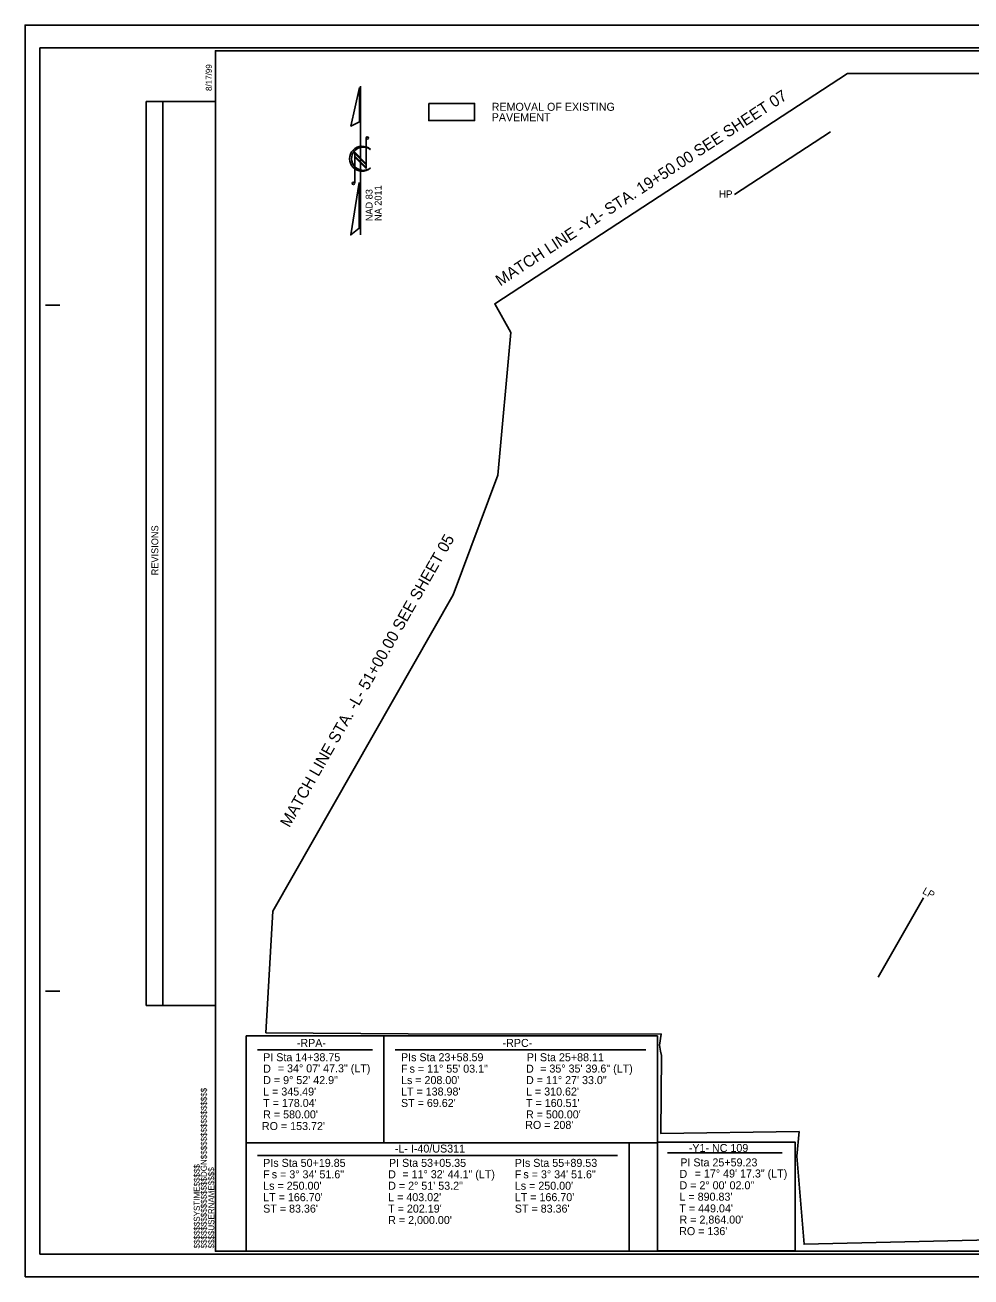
# Model space of a CAD drawing. Extents: x 1639431 to 1642602, y 841916 to 843940.
# Drawn here: x 1640204 to 1641031, y 841916 to 843011 of the extents above; entities that cross this region are included whole.
import ezdxf

# ---------------------------------------------------------------- set-up
doc = ezdxf.new("R2010")
doc.units = 0
for name, color, linetype in [('Default', 7, 'Continuous'), ('Matchline', 7, 'Continuous'), ('Matchline Text', 7, 'Continuous'), ('Old_Level_1', 7, 'Continuous'), ('Prop Horizontal Alignment Curve and Spiral Data', 7, 'Continuous'), ('Prop Rem of Exist Asph Pvmt', 7, 'Continuous'), ('Sheet Block Revision CELL', 7, 'Continuous'), ('Sheet Clip Boundary CELL', 7, 'Continuous'), ('Sheet Cutting Line CELL', 7, 'Continuous'), ('Sheet North Arrow CELL', 7, 'Continuous'), ('Sheet Plan CELL', 7, 'Continuous'), ('Sheet Plot Border Inside CELL', 7, 'Continuous'), ('Sheet Plot Border Outside CELL', 7, 'Continuous')]:
    doc.layers.add(name, color=color, linetype=linetype)

msp = doc.modelspace()

# ---------------------------------------------------------------- linework, layer by layer
at = {"layer": 'Matchline'}
msp.add_lwpolyline([(1640420.8, 842236.2), (1640420.8, 842236.2), (1640578.7, 842512.8), (1640617.7, 842617.6), (1640629.1, 842742.4), (1640615, 842767.5), (1640923.5, 842968.8)], dxfattribs=at)
at = {"layer": 'Old_Level_1'}
for p, q in [((1640908.4, 842917.8), (1640824.6, 842863.2)), ((1640950.2, 842178.6), (1640989.8, 842248))]:
    msp.add_line(p, q, dxfattribs=at)
at = {"layer": 'Prop Horizontal Alignment Curve and Spiral Data'}
for p, q in [((1640407.5, 842115), (1640508, 842115)), ((1640528, 842115), (1640747.2, 842115)), ((1640407.5, 842022.6), (1640722.4, 842022.6)), ((1640765.9, 842024.9), (1640866.4, 842024.9))]:
    msp.add_line(p, q, dxfattribs=at)
for points in [[(1640397.5, 842127.2), (1640518, 842127.2), (1640518, 842033.7), (1640397.5, 842033.7)], [(1640518, 842127.2), (1640757.2, 842127.2), (1640757.2, 842033.7), (1640518, 842033.7)], [(1640397.5, 842033.7), (1640732.4, 842033.7), (1640732.4, 841938.8), (1640397.5, 841938.8)], [(1640757.2, 842034.2), (1640877.7, 842034.2), (1640877.7, 841939.3), (1640757.2, 841939.3)]]:
    msp.add_lwpolyline(points, close=True, dxfattribs=at)
at = {"layer": 'Prop Rem of Exist Asph Pvmt'}
msp.add_lwpolyline([(1640557.3, 842942.7), (1640557.3, 842927.7), (1640597.3, 842927.7), (1640597.3, 842942.7)], close=True, dxfattribs=at)
at = {"layer": 'Sheet Block Revision CELL'}
msp.add_line((1640324.8, 842153.8), (1640324.8, 842944.5), dxfattribs=at)
msp.add_lwpolyline([(1640310.3, 842153.8), (1640310.3, 842944.4), (1640370.8, 842944.5), (1640370.8, 842153.8)], close=True, dxfattribs=at)
at = {"layer": 'Sheet Clip Boundary CELL'}
msp.add_line((1640923.5, 842968.8), (1641358.9, 842968.8), dxfattribs=at)
for points in [[(1640414.8, 842129.8), (1640420.8, 842236.2), (1640578.7, 842512.8), (1640617.7, 842617.6), (1640629.1, 842742.4), (1640615, 842767.5), (1640923.5, 842968.8)], [(1641627.1, 841958.8), (1641476.3, 841958.8), (1640885.4, 841944.9), (1640879, 842022.1), (1640881.1, 842043.4), (1640760.2, 842041.7), (1640760.7, 842110.1), (1640760, 842113.9), (1640759.1, 842119), (1640760.5, 842128.8), (1640539.4, 842129), (1640414.8, 842129.8)]]:
    msp.add_lwpolyline(points, dxfattribs=at)
at = {"layer": 'Sheet Cutting Line CELL'}
for p, q in [((1640204.3, 843011.3), (1640204.3, 841916.3)), ((1640204.3, 841916.3), (1641887.8, 841916.3))]:
    msp.add_line(p, q, dxfattribs=at)
at = {"layer": 'Sheet North Arrow CELL'}
for p, q in [((1640497.5, 842827.8), (1640497.5, 842957.8)), ((1640502.4, 842912.6), (1640502.4, 842885.9)), ((1640502.4, 842890), (1640492.5, 842900)), ((1640492.5, 842900), (1640492.5, 842872.9)), ((1640502.4, 842889.1), (1640492.5, 842899)), ((1640492.5, 842899), (1640492.5, 842896.6)), ((1640506.1, 842902.6), (1640506.3, 842902.5)), ((1640502.4, 842886.6), (1640492.5, 842896.6)), ((1640492.5, 842896.6), (1640502.4, 842886.6)), ((1640502.4, 842885.9), (1640492.5, 842895.8)), ((1640502.4, 842886.6), (1640502.4, 842889.1))]:
    msp.add_line(p, q, dxfattribs=at)
for points in [[(1640496.6, 842956.7), (1640489.2, 842922.9), (1640496.6, 842926.7)], [(1640496.5, 842873.6), (1640489.1, 842827.8), (1640496.5, 842833.6)]]:
    msp.add_lwpolyline(points, close=True, dxfattribs=at)
for centre in [(1640503.5, 842912.5), (1640491.4, 842872.8)]:
    msp.add_circle(centre, 1.06, dxfattribs=at)
for centre, radius, start, end in [((1640498.9, 842894.4), 10.9, 47.84, 312.3941), ((1640500, 842894.4), 10.2, 53.095, 308.6287)]:
    msp.add_arc(centre, radius, start, end, dxfattribs=at)
at = {"layer": 'Sheet Plan CELL'}
for p, q in [((1640370.8, 842988.8), (1640370.8, 842988.8)), ((1640222.3, 842766.3), (1640234.8, 842766.3)), ((1640222.3, 842166.3), (1640234.8, 842166.3)), ((1640370.8, 841938.8), (1640370.8, 841938.8))]:
    msp.add_line(p, q, dxfattribs=at)
for points in [[(1641870.8, 842988.8), (1640370.8, 842988.8), (1640370.8, 841938.8), (1641870.8, 841938.8)], [(1640370.8, 841938.8), (1640370.8, 842988.8), (1641670.8, 842988.8), (1641670.8, 842838.8), (1641870.8, 842838.8), (1641870.8, 841938.8)]]:
    msp.add_lwpolyline(points, close=True, dxfattribs=at)
at = {"layer": 'Sheet Plot Border Inside CELL'}
msp.add_lwpolyline([(1640217.3, 841936.3), (1641883.3, 841936.3), (1641883.3, 842991.3), (1640217.3, 842991.3)], close=True, dxfattribs=at)
at = {"layer": 'Sheet Plot Border Outside CELL'}
msp.add_lwpolyline([(1640204.3, 841916.3), (1641887.8, 841916.3), (1641887.8, 843011.3), (1640204.3, 843011.3)], close=True, dxfattribs=at)
msp.add_lwpolyline([(1640204.3, 841916.3), (1641887.8, 841916.3), (1641887.8, 843011.3), (1640204.3, 843011.3)], close=True, dxfattribs=at)

# ---------------------------------------------------------------- texts
at = {"layer": 'Default'}
for s, p in [('REMOVAL OF EXISTING', (1640612.3, 842936.3)), ('PAVEMENT', (1640612.3, 842927.2))]:
    msp.add_text(s, height=7, dxfattribs=at).set_placement(p)
at = {"layer": 'Matchline Text'}
for s, rotation, p in [('MATCH LINE -Y1- STA. 19+50.00 SEE SHEET 07', 33.1259, (1640619.8, 842782.6)), ('MATCH LINE STA. -L- 51+00.00 SEE SHEET 05', 60.2753, (1640435.4, 842308.8))]:
    msp.add_text(s, height=10, rotation=rotation, dxfattribs=at).set_placement(p)
at = {"layer": 'Old_Level_1'}
msp.add_text('HP', height=6.37, dxfattribs=at).set_placement((1640811, 842860.3))
msp.add_text('LP', height=6.37, rotation=330.2753, dxfattribs=at).set_placement((1640988.3, 842252.1))
at = {"layer": 'Prop Horizontal Alignment Curve and Spiral Data'}
for s, p in [('-RPA-', (1640441.9, 842117.5)), ('-RPC-', (1640621.8, 842117.5)), ('PI Sta 14+38.75', (1640412.5, 842105)), ('PIs Sta 23+58.59', (1640533, 842105)), ('PI Sta 25+88.11', (1640643, 842105)), ('D', (1640412.5, 842095)), ('= 34%%d 07\' 47.3" (LT)', (1640425.3, 842095.3)), ('F', (1640533, 842095)), ('s = 11%%d 55\' 03.1"', (1640540.5, 842095)), ('D', (1640642.3, 842095)), ('= 35%%d 35\' 39.6" (LT)', (1640654.7, 842095.1)), ('D = 9%%d 52\' 42.9"', (1640412.5, 842085)), ("Ls = 208.00'", (1640533, 842085)), ('D = 11%%d 27\' 33.0"', (1640642.3, 842085)), ("L = 345.49'", (1640412.5, 842075)), ("LT = 138.98'", (1640533, 842075)), ("L = 310.62'", (1640642.3, 842075)), ("T = 178.04'", (1640412.5, 842065)), ("ST = 69.62'", (1640533, 842065)), ("T = 160.51'", (1640642.3, 842065)), ("R = 580.00'", (1640412.5, 842055)), ("R = 500.00'", (1640642.3, 842055)), ("RO = 153.72'", (1640411.4, 842044.8)), ("RO = 208'", (1640641.6, 842045.8)), ('-L- I-40/US311', (1640527.6, 842025.1)), ('-Y1- NC 109', (1640784.6, 842025.6)), ('PIs Sta 50+19.85', (1640412.5, 842012.6)), ('PI Sta 53+05.35', (1640522.5, 842012.6)), ('PIs Sta 55+89.53', (1640632.5, 842012.6)), ('PI Sta 25+59.23', (1640777.2, 842013)), ('F', (1640412.5, 842002.6)), ('s = 3%%d 34\' 51.6"', (1640420, 842002.6)), ('D', (1640521.8, 842002.6)), ('= 11%%d 32\' 44.1" (LT)', (1640534.2, 842002.7)), ('F', (1640632.5, 842002.6)), ('s = 3%%d 34\' 51.6"', (1640640, 842002.6)), ('D', (1640776.5, 842003)), ('= 17%%d 49\' 17.3" (LT)', (1640789.8, 842003.3)), ("Ls = 250.00'", (1640412.5, 841992.6)), ("LT = 166.70'", (1640412.5, 841982.6)), ('D = 2%%d 51\' 53.2"', (1640521.8, 841992.6)), ("L = 403.02'", (1640521.8, 841982.6)), ("Ls = 250.00'", (1640632.5, 841992.6)), ("LT = 166.70'", (1640632.5, 841982.6)), ('D = 2%%d 00\' 02.0"', (1640776.5, 841993)), ("L = 890.83'", (1640776.5, 841983)), ("ST = 83.36'", (1640412.5, 841972.6)), ("T = 202.19'", (1640521.8, 841972.6)), ("ST = 83.36'", (1640632.5, 841972.6)), ("T = 449.04'", (1640776.4, 841972.8)), ("R = 2,000.00'", (1640521.8, 841962.6)), ("R = 2,864.00'", (1640776.5, 841963)), ("RO = 136'", (1640776.2, 841952.9))]:
    msp.add_text(s, height=7, dxfattribs=at).set_placement(p)
at = {"layer": 'Sheet Block Revision CELL'}
msp.add_text('REVISIONS', height=6, rotation=90, dxfattribs=at).set_placement((1640320.8, 842530))
at = {"layer": 'Sheet North Arrow CELL'}
for s, p in [('NAD 83', (1640508.1, 842839.7)), ('NA 2011', (1640516, 842839.9))]:
    msp.add_text(s, height=6, rotation=90, dxfattribs=at).set_placement(p)
at = {"layer": 'Sheet Plan CELL'}
for s, p in [('8/17/99', (1640367.6, 842953.6)), ('$$$$$$$$$$$$$$$$DGN$$$$$$$$$$$$$$$$', (1640363.2, 841941.2)), ('$$$$$$SYSTIME$$$$$', (1640357.1, 841941.2)), ('$$$$USERNAME$$$$', (1640369.7, 841941.2))]:
    msp.add_text(s, height=5.25, rotation=90, dxfattribs=at).set_placement(p)

doc.saveas('drawing.dxf')
